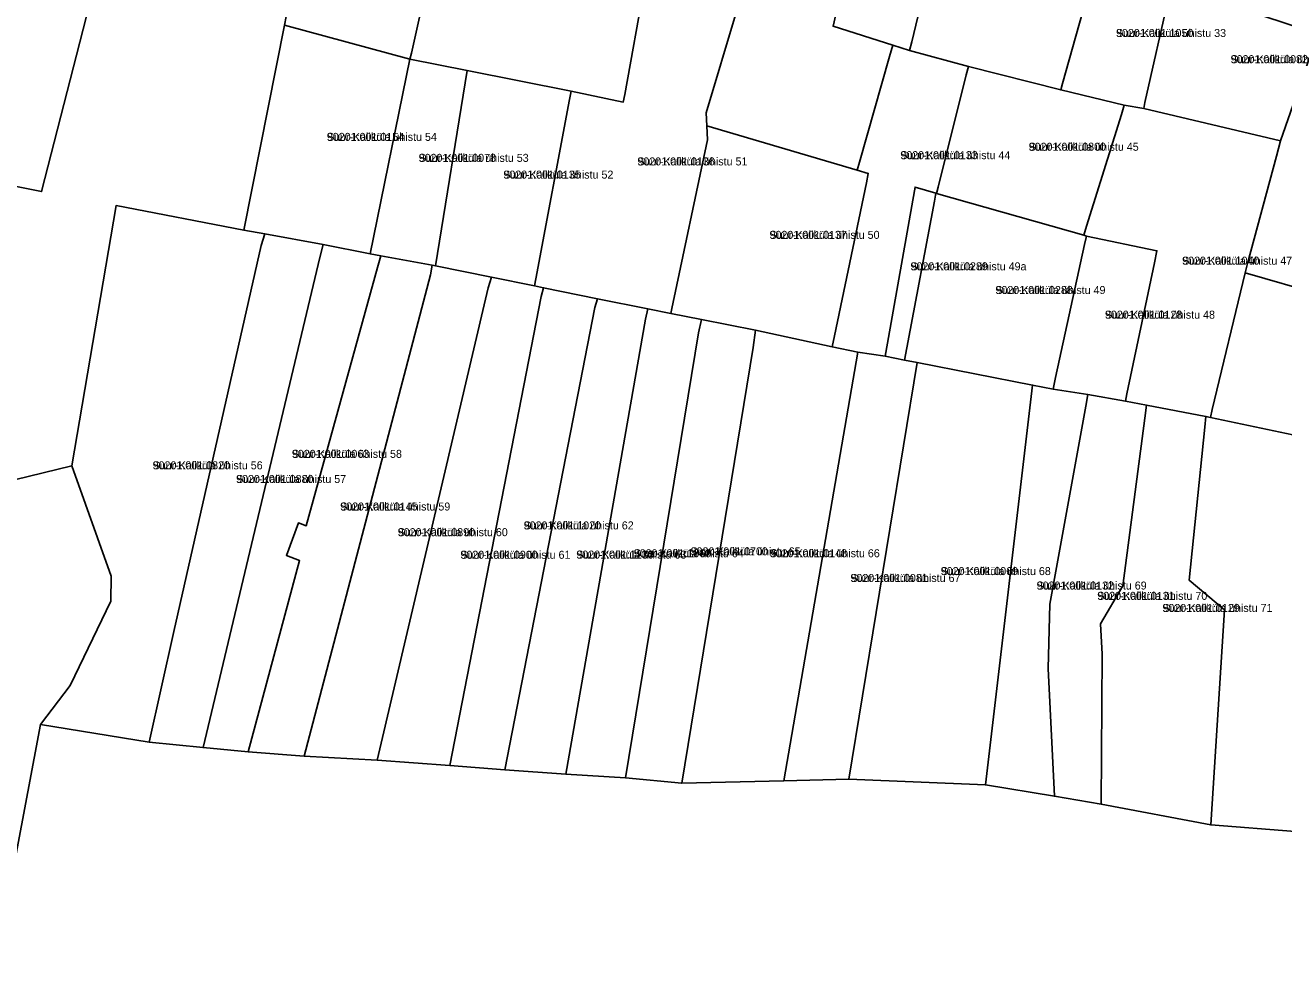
# Model space of a CAD drawing. Extents: x 634518 to 667988, y 6584667 to 6604739.
# Drawn here: x 639044.6 to 639280.5, y 6598757.6 to 6598932.5 of the extents above; entities that cross this region are included whole.
import ezdxf

# ---------------------------------------------------------------- set-up
doc = ezdxf.new("R2010")
doc.units = 0
for name, color, linetype in [('L_AADRESS', 7, 'Continuous'), ('PIIR', 7, 'Continuous'), ('TUNNUS', 7, 'Continuous')]:
    doc.layers.add(name, color=color, linetype=linetype)

msp = doc.modelspace()

# ---------------------------------------------------------------- linework, layer by layer
at = {"layer": 'PIIR'}
for points in [[(638939.52, 6598922.84), (638956.22, 6599045.86), (638963.81, 6599131.43), (639036.47, 6599305.14), (639066.16, 6599272.46), (639113.06, 6599217.03), (639136.09, 6599200.35), (639153.39, 6599188.58), (639173.59, 6599187.14), (639118.65, 6599126.67), (639114.82, 6599117.34), (639093.64, 6599086.65), (639078.76, 6599065.25), (639063.55, 6599043.7), (639051.11, 6599025.24), (639040.95, 6598997.58), (639033.5, 6598975.34), (639064.36, 6598966.67), (639057.8, 6598941.11), (639047.63, 6598901.35)], [(639186.87, 6598957.3), (639200.79, 6598953.74), (639200.67, 6598953.2), (639199.3, 6598947.05), (639196.2, 6598933.19), (639196.01, 6598932.34), (639207.23, 6598928.76), (639206.63, 6598926.69), (639200.95, 6598906.88), (639200.52, 6598905.37), (639172.35, 6598913.64), (639172.21, 6598916.11), (639177.91, 6598935.09), (639178.65, 6598937.56), (639181.22, 6598937.04), (639181.54, 6598937.98)], [(639100.43, 6598954.77), (639102.61, 6598954.25), (639117.04, 6598950.79), (639121.91, 6598949.63), (639121.56, 6598947.93), (639117.01, 6598927.26), (639116.7, 6598926.17), (639093.18, 6598932.53), (639093.52, 6598934.15)], [(639196.2, 6598933.19), (639199.3, 6598947.05), (639200.79, 6598953.74), (639201.23, 6598955.56), (639202.11, 6598955.44), (639216.08, 6598951.66), (639215.67, 6598949.8), (639210.76, 6598929.39), (639210.33, 6598927.78), (639207.23, 6598928.76), (639196.01, 6598932.34)], [(639210.33, 6598927.78), (639210.76, 6598929.39), (639215.67, 6598949.8), (639216.08, 6598951.66), (639216.79, 6598951.47), (639229.71, 6598947.85), (639244.99, 6598943.84), (639244.7, 6598941.84), (639239.04, 6598921.58), (639238.71, 6598920.4), (639221.4, 6598924.82)], [(639117.01, 6598927.26), (639121.56, 6598947.93), (639121.91, 6598949.63), (639138.28, 6598945.61), (639160.85, 6598941.12), (639160.67, 6598940.12), (639156.96, 6598919.57), (639156.68, 6598918.13), (639146.93, 6598920.16), (639127.44, 6598924.03), (639116.7, 6598926.17)], [(639239.04, 6598921.58), (639244.7, 6598941.84), (639244.99, 6598943.84), (639257.47, 6598940.45), (639259.44, 6598939.94), (639259.01, 6598938.25), (639254.49, 6598918.07), (639254.25, 6598916.93), (639250.61, 6598917.53), (639238.71, 6598920.4)], [(638939.52, 6598922.84), (639047.63, 6598901.35), (639057.8, 6598941.11), (639093.52, 6598934.15), (639093.18, 6598932.53), (639085.55, 6598894.14), (639061.6, 6598898.73), (639053.29, 6598849.93), (638932.7, 6598820.51)], [(639160.85, 6598941.12), (639178.65, 6598937.56), (639177.91, 6598935.09), (639172.21, 6598916.11), (639172.35, 6598913.64), (639172.49, 6598911.07), (639165.79, 6598879.46), (639165.59, 6598878.52), (639161.31, 6598879.37), (639151.84, 6598881.28), (639141.76, 6598883.34), (639140.02, 6598883.69), (639140.27, 6598885), (639146.63, 6598918.6), (639146.93, 6598920.16), (639156.68, 6598918.13), (639156.96, 6598919.57), (639160.67, 6598940.12)], [(639259.01, 6598938.25), (639259.44, 6598939.94), (639270.78, 6598936.2), (639286.75, 6598930.92), (639285.94, 6598928.24), (639279.92, 6598910.88), (639254.25, 6598916.93), (639254.49, 6598918.07)], [(639093.18, 6598932.53), (639116.7, 6598926.17), (639109.23, 6598889.69), (639100.42, 6598891.46), (639089.47, 6598893.4), (639085.55, 6598894.14)], [(639285.94, 6598928.24), (639286.75, 6598930.92), (639296.8, 6598926.09), (639313.51, 6598915.58), (639302.64, 6598880.07), (639301.91, 6598877.89), (639273.27, 6598886.15), (639273.71, 6598887.89), (639279.15, 6598907.98), (639279.92, 6598910.88)], [(639207.23, 6598928.76), (639210.33, 6598927.78), (639221.4, 6598924.82), (639221, 6598923.23), (639215.74, 6598902.17), (639215.44, 6598900.99), (639215.3, 6598901.03), (639211.41, 6598902.18), (639210.97, 6598899.71), (639206.23, 6598872.96), (639205.79, 6598870.48), (639200.64, 6598871.24), (639195.87, 6598872.28), (639196.3, 6598874.33), (639202.27, 6598903.01), (639202.63, 6598904.75), (639200.52, 6598905.37), (639200.95, 6598906.88), (639206.63, 6598926.69)], [(639116.7, 6598926.17), (639127.44, 6598924.03), (639121.5, 6598887.43), (639120.87, 6598887.53), (639111.22, 6598889.29), (639109.23, 6598889.69)], [(639127.44, 6598924.03), (639146.93, 6598920.16), (639146.63, 6598918.6), (639140.27, 6598885), (639140.02, 6598883.69), (639131.98, 6598885.32), (639121.5, 6598887.43)], [(639215.74, 6598902.17), (639221, 6598923.23), (639221.4, 6598924.82), (639238.71, 6598920.4), (639250.61, 6598917.53), (639250.07, 6598915.8), (639243.53, 6598894.86), (639243.01, 6598893.17), (639215.44, 6598900.99)], [(639251.09, 6598863.42), (639256.26, 6598887.99), (639256.73, 6598890.26), (639243.53, 6598893.02), (639243.01, 6598893.17), (639243.53, 6598894.86), (639250.07, 6598915.8), (639250.61, 6598917.53), (639254.25, 6598916.93), (639279.92, 6598910.88), (639279.15, 6598907.98), (639273.71, 6598887.89), (639273.27, 6598886.15), (639267.12, 6598860.53), (639266.77, 6598859.03), (639265.93, 6598859.21), (639254.77, 6598861.34), (639250.82, 6598862.09)], [(639172.35, 6598913.64), (639200.52, 6598905.37), (639202.63, 6598904.75), (639202.27, 6598903.01), (639196.3, 6598874.33), (639195.87, 6598872.28), (639181.49, 6598875.36), (639171.36, 6598877.37), (639165.59, 6598878.52), (639165.79, 6598879.46), (639172.49, 6598911.07)], [(639211.41, 6598902.18), (639215.3, 6598901.03), (639215.02, 6598899.57), (639209.83, 6598872.07), (639209.4, 6598869.78), (639205.79, 6598870.48), (639206.23, 6598872.96), (639210.97, 6598899.71)], [(639215.3, 6598901.03), (639215.44, 6598900.99), (639243.01, 6598893.17), (639243.53, 6598893.02), (639243.18, 6598891.44), (639237.74, 6598866.52), (639237.26, 6598864.33), (639233.42, 6598865.09), (639211.77, 6598869.31), (639209.4, 6598869.78), (639209.83, 6598872.07), (639215.02, 6598899.57)], [(639089.47, 6598893.4), (639088.84, 6598891.27), (639072.42, 6598818.92), (639067.79, 6598798.19), (639047.45, 6598801.49), (639053.02, 6598808.8), (639060.61, 6598824.61), (639060.67, 6598829.3), (639053.29, 6598849.93), (639061.6, 6598898.73), (639085.55, 6598894.14)], [(639067.79, 6598798.19), (639072.42, 6598818.92), (639088.84, 6598891.27), (639089.47, 6598893.4), (639100.42, 6598891.46), (639099.82, 6598888.97), (639077.92, 6598797.15)], [(639243.53, 6598893.02), (639256.73, 6598890.26), (639256.26, 6598887.99), (639251.09, 6598863.42), (639250.82, 6598862.09), (639243.78, 6598863.34), (639237.26, 6598864.33), (639237.74, 6598866.52), (639243.18, 6598891.44)], [(639099.82, 6598888.97), (639100.42, 6598891.46), (639109.23, 6598889.69), (639111.22, 6598889.29), (639110.64, 6598887.14), (639097.25, 6598838.72), (639095.8, 6598839.26), (639093.55, 6598833.18), (639096, 6598832.21), (639086.39, 6598796.37), (639077.92, 6598797.15)], [(639111.22, 6598889.29), (639120.87, 6598887.53), (639120.55, 6598885.74), (639096.85, 6598795.57), (639086.39, 6598796.37), (639096, 6598832.21), (639093.55, 6598833.18), (639095.8, 6598839.26), (639097.25, 6598838.72), (639110.64, 6598887.14)], [(639120.55, 6598885.74), (639120.87, 6598887.53), (639121.5, 6598887.43), (639131.98, 6598885.32), (639131.36, 6598883.33), (639110.57, 6598794.77), (639096.85, 6598795.57)], [(639110.57, 6598794.77), (639131.36, 6598883.33), (639131.98, 6598885.32), (639140.02, 6598883.69), (639141.76, 6598883.34), (639141.29, 6598881.68), (639124.2, 6598793.78)], [(639267.12, 6598860.53), (639273.27, 6598886.15), (639301.91, 6598877.89), (639292.87, 6598853.52), (639266.77, 6598859.03)], [(639124.2, 6598793.78), (639141.29, 6598881.68), (639141.76, 6598883.34), (639151.84, 6598881.28), (639151.35, 6598879.6), (639134.46, 6598792.96)], [(639134.46, 6598792.96), (639151.35, 6598879.6), (639151.84, 6598881.28), (639161.31, 6598879.37), (639160.84, 6598877.44), (639145.94, 6598792.18)], [(639145.94, 6598792.18), (639160.84, 6598877.44), (639161.31, 6598879.37), (639165.59, 6598878.52), (639171.36, 6598877.37), (639170.79, 6598874.85), (639157.13, 6598791.46)], [(639181.49, 6598875.36), (639181.04, 6598872.1), (639167.66, 6598790.48), (639157.13, 6598791.46), (639170.79, 6598874.85), (639171.36, 6598877.37)], [(639181.49, 6598875.36), (639195.87, 6598872.28), (639200.64, 6598871.24), (639186.79, 6598790.92), (639167.66, 6598790.48), (639181.04, 6598872.1)], [(639200.64, 6598871.24), (639205.79, 6598870.48), (639209.4, 6598869.78), (639211.77, 6598869.31), (639198.99, 6598791.25), (639186.79, 6598790.92)], [(639211.77, 6598869.31), (639233.42, 6598865.09), (639224.57, 6598790.15), (639198.99, 6598791.25)], [(639233.42, 6598865.09), (639237.26, 6598864.33), (639243.78, 6598863.34), (639243.38, 6598861.14), (639236.66, 6598824.03), (639236.32, 6598811.97), (639237.51, 6598788.05), (639224.57, 6598790.15)], [(639243.78, 6598863.34), (639250.82, 6598862.09), (639254.77, 6598861.34), (639254.45, 6598858.89), (639250.36, 6598827.47), (639246.14, 6598820.36), (639246.45, 6598814.64), (639246.31, 6598786.53), (639237.51, 6598788.05), (639236.32, 6598811.97), (639236.66, 6598824.03), (639243.38, 6598861.14)], [(639254.77, 6598861.34), (639265.93, 6598859.21), (639265.72, 6598857.2), (639262.79, 6598828.52), (639269.39, 6598822.96), (639266.83, 6598782.66), (639246.31, 6598786.53), (639246.45, 6598814.64), (639246.14, 6598820.36), (639250.36, 6598827.47), (639254.45, 6598858.89)], [(639269.39, 6598822.96), (639262.79, 6598828.52), (639265.72, 6598857.2), (639265.93, 6598859.21), (639266.77, 6598859.03), (639292.87, 6598853.52), (639287.46, 6598832.3), (639287.63, 6598822.58), (639290.12, 6598814.94), (639299.29, 6598804.06), (639298.45, 6598780.16), (639266.83, 6598782.66)], [(638865.68, 6598809.66), (638932.7, 6598820.51), (639053.29, 6598849.93), (639060.67, 6598829.3), (639060.61, 6598824.61), (639053.02, 6598808.8), (639047.45, 6598801.49), (639020.26, 6598657.37), (639002, 6598650.78), (639014.44, 6598717.35), (638928.95, 6598735.62), (638888.41, 6598738.83), (638859.4, 6598736.86)]]:
    msp.add_lwpolyline(points, close=True, dxfattribs=at)
msp.add_lwpolyline([(639020.26, 6598657.37), (639047.45, 6598801.49), (639067.79, 6598798.19), (639077.92, 6598797.15), (639086.39, 6598796.37), (639096.85, 6598795.57), (639110.57, 6598794.77), (639124.2, 6598793.78), (639134.46, 6598792.96), (639145.94, 6598792.18), (639157.13, 6598791.46), (639167.66, 6598790.48), (639186.79, 6598790.92), (639198.99, 6598791.25), (639224.57, 6598790.15), (639237.51, 6598788.05), (639246.31, 6598786.53), (639266.83, 6598782.66), (639298.45, 6598780.16), (639331.83, 6598777.4), (639403.21, 6598762.87), (639404.8, 6598794.89), (639410.81, 6598792.11)], dxfattribs=at)

# ---------------------------------------------------------------- texts
at = {"layer": 'L_AADRESS'}
for s, p in [('Suur-Kaliküla ühistu 33', (639249.07, 6598930.32)), ('Suur-Kaliküla ühistu 32', (639270.55, 6598925.41)), ('Suur-Kaliküla ühistu 54', (639101.12, 6598910.85)), ('Suur-Kaliküla ühistu 53', (639118.33, 6598906.92)), ('Suur-Kaliküla ühistu 44', (639208.63, 6598907.42)), ('Suur-Kaliküla ühistu 45', (639232.69, 6598909)), ('Suur-Kaliküla ühistu 51', (639159.34, 6598906.25)), ('Suur-Kaliküla ühistu 52', (639134.21, 6598903.78)), ('Suur-Kaliküla ühistu 50', (639184.11, 6598892.49)), ('Suur-Kaliküla ühistu 49a', (639210.54, 6598886.59)), ('Suur-Kaliküla ühistu 47', (639261.46, 6598887.65)), ('Suur-Kaliküla ühistu 49', (639226.46, 6598882.15)), ('Suur-Kaliküla ühistu 48', (639246.99, 6598877.53)), ('Suur-Kaliküla ühistu 58', (639094.57, 6598851.45)), ('Suur-Kaliküla ühistu 56', (639068.46, 6598849.3)), ('Suur-Kaliküla ühistu 57', (639084.11, 6598846.74)), ('Suur-Kaliküla ühistu 59', (639103.63, 6598841.58)), ('Suur-Kaliküla ühistu 60', (639114.41, 6598836.77)), ('Suur-Kaliküla ühistu 62', (639138.02, 6598838.04)), ('Suur-Kaliküla ühistu 61', (639126.16, 6598832.54)), ('Suur-Kaliküla ühistu 63', (639147.89, 6598832.57)), ('Suur-Kaliküla ühistu 64', (639158.65, 6598832.82)), ('Suur-Kaliküla ühistu 65', (639169.31, 6598833.18)), ('Suur-Kaliküla ühistu 66', (639184.15, 6598832.82)), ('Suur-Kaliküla ühistu 68', (639216.21, 6598829.48)), ('Suur-Kaliküla ühistu 67', (639199.28, 6598828.19)), ('Suur-Kaliküla ühistu 69', (639234.18, 6598826.77)), ('Suur-Kaliküla ühistu 70', (639245.55, 6598824.84)), ('Suur-Kaliküla ühistu 71', (639257.77, 6598822.57))]:
    msp.add_text(s, height=1.5, dxfattribs=at).set_placement(p)
at = {"layer": 'TUNNUS'}
for s, p in [('90201:001:1050', (639249.07, 6598930.32)), ('90201:001:0082', (639270.55, 6598925.41)), ('90201:001:0154', (639101.12, 6598910.85)), ('90201:001:0133', (639208.63, 6598907.42)), ('90201:001:0800', (639232.69, 6598909)), ('90201:001:0078', (639118.33, 6598906.92)), ('90201:001:0136', (639159.34, 6598906.25)), ('90201:001:0135', (639134.21, 6598903.78)), ('90201:001:0137', (639184.11, 6598892.49)), ('90201:001:0289', (639210.54, 6598886.59)), ('90201:001:1040', (639261.46, 6598887.65)), ('90201:001:0288', (639226.46, 6598882.15)), ('90201:001:0128', (639246.99, 6598877.53)), ('90201:001:0063', (639094.57, 6598851.45)), ('90201:001:0820', (639068.46, 6598849.3)), ('90201:001:0880', (639084.11, 6598846.74)), ('90201:001:0145', (639103.63, 6598841.58)), ('90201:001:0890', (639114.41, 6598836.77)), ('90201:001:1020', (639138.02, 6598838.04)), ('90201:001:0900', (639126.16, 6598832.54)), ('90201:001:1130', (639147.89, 6598832.57)), ('90201:001:1060', (639158.65, 6598832.82)), ('90201:001:0700', (639169.31, 6598833.18)), ('90201:001:0148', (639184.15, 6598832.82)), ('90201:001:0069', (639216.21, 6598829.48)), ('90201:001:0081', (639199.28, 6598828.19)), ('90201:001:0132', (639234.18, 6598826.77)), ('90201:001:0131', (639245.55, 6598824.84)), ('90201:001:0129', (639257.77, 6598822.57))]:
    msp.add_text(s, height=1.5, dxfattribs=at).set_placement(p)

doc.saveas('drawing.dxf')
